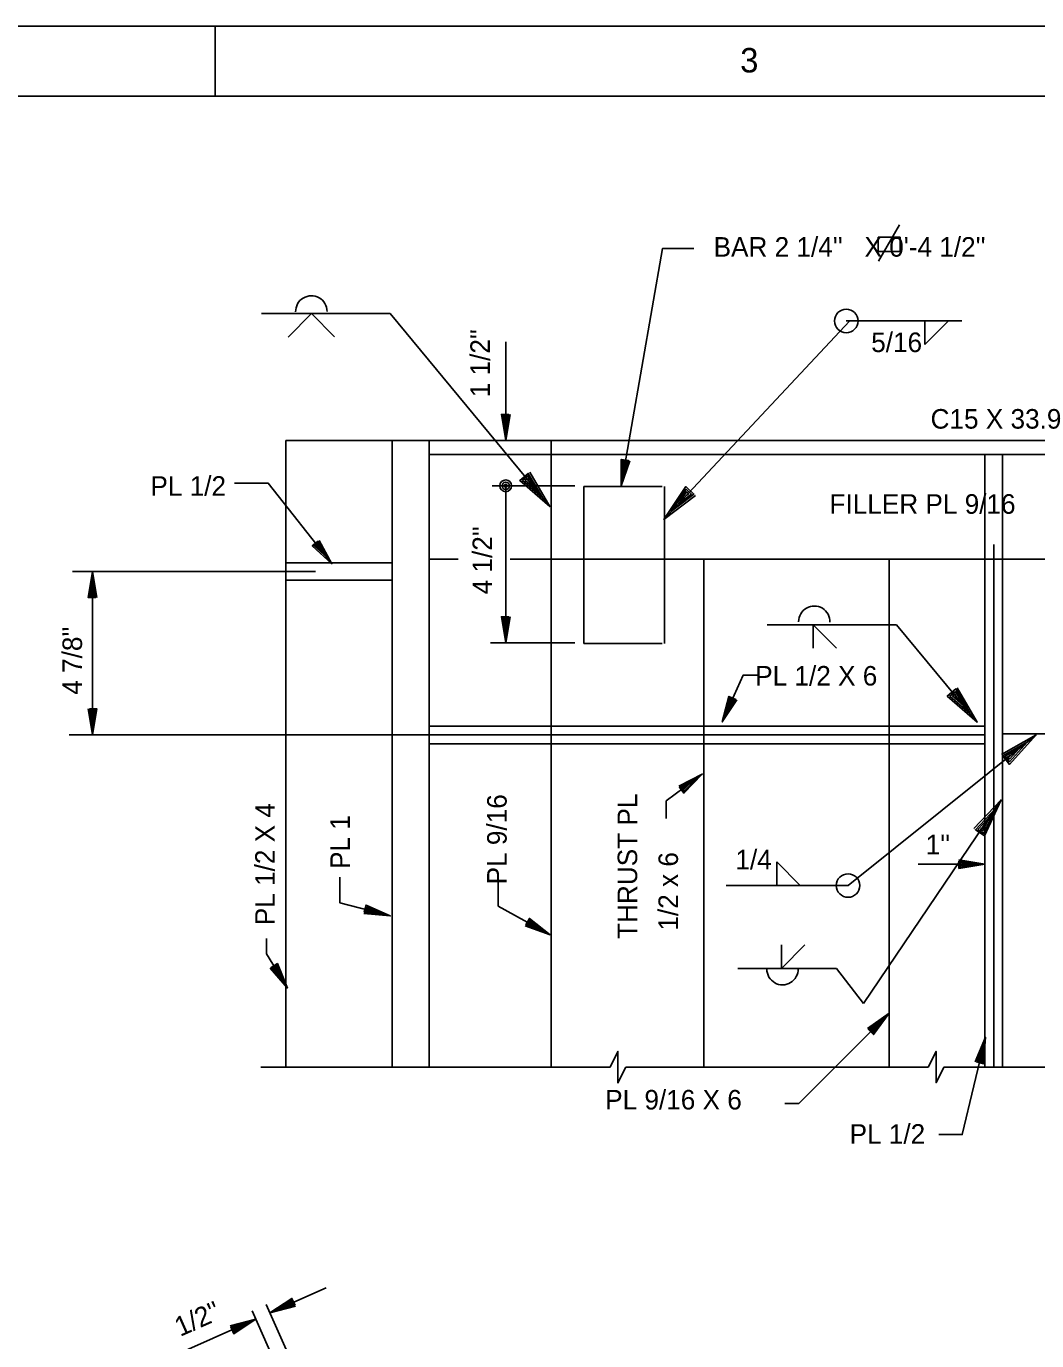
# Model space of a CAD drawing. Extents: x 0.1 to 13.5, y 0.1 to 9.5.
# Drawn here: x 5.215 to 7.629, y 6.319 to 9.458 of the extents above; entities that cross this region are included whole.
import ezdxf

# ---------------------------------------------------------------- set-up
doc = ezdxf.new("R2010")
doc.units = 0
for name, color, linetype in [('Level 1', 7, 'Continuous'), ('Level 13', 7, 'Continuous'), ('Level 25', 7, 'Continuous'), ('Level 3', 7, 'Continuous'), ('Level 50', 7, 'Continuous')]:
    doc.layers.add(name, color=color, linetype=linetype)

msp = doc.modelspace()

# ---------------------------------------------------------------- linework, layer by layer
at = {"layer": 'Level 1'}
for p, q in [((5.6667, 9.2917), (5.6667, 9.4583)), ((6.3284, 8.361), (6.5259, 8.361)), ((6.3244, 7.986), (6.5259, 7.986)), ((7.3455, 7.4575), (7.5053, 7.4575)), ((5.7753, 6.9726), (6.6097, 6.9726)), ((6.6471, 6.9726), (7.3699, 6.9726)), ((7.4072, 6.9726), (7.8241, 6.9726))]:
    msp.add_line(p, q, dxfattribs=at)
for points in [[(0.125, 9.4583), (13.4583, 9.4583), (13.4583, 0.125), (0.125, 0.125)], [(0.625, 9.2917), (13.2917, 9.2917), (13.2917, 0.2917), (0.625, 0.2917)]]:
    msp.add_lwpolyline(points, close=True, dxfattribs=at)
at = {"layer": 'Level 13'}
for points in [[(6.6471, 6.9726), (6.6284, 6.9351), (6.6284, 7.0101), (6.6097, 6.9726)], [(7.3699, 6.9726), (7.3885, 7.0101), (7.3885, 6.9352), (7.4072, 6.9726)]]:
    msp.add_lwpolyline(points, dxfattribs=at)
at = {"layer": 'Level 25'}
for p, q in [((7.3009, 8.9838), (7.2512, 8.8977)), ((7.3027, 8.9545), (7.2503, 8.9545)), ((7.2503, 8.9545), (7.2503, 8.9202)), ((7.3027, 8.9545), (7.3027, 8.9202)), ((7.3027, 8.9202), (7.2503, 8.9202)), ((6.0842, 8.7722), (5.7769, 8.7722)), ((5.8967, 8.7722), (5.8407, 8.7162)), ((5.8964, 8.7722), (5.8965, 8.7721)), ((5.8965, 8.7721), (5.9519, 8.7167)), ((6.0842, 8.7722), (6.4657, 8.3113)), ((7.1813, 8.7545), (6.7383, 8.2803)), ((7.174, 8.7546), (7.4498, 8.7546)), ((7.3615, 8.7546), (7.3615, 8.6984)), ((7.3615, 8.6984), (7.4173, 8.7542)), ((6.3606, 8.469), (6.3606, 8.7049)), ((5.8356, 8.469), (8.6378, 8.469)), ((5.8356, 8.469), (5.8356, 6.9726)), ((6.0894, 8.469), (6.0894, 6.9726)), ((6.1774, 8.469), (6.1774, 6.9726)), ((6.4689, 8.469), (6.4689, 6.9726)), ((6.1774, 8.4357), (8.6378, 8.4357)), ((7.5053, 8.4357), (7.5053, 6.9726)), ((7.547, 8.4357), (7.547, 6.9726)), ((6.3606, 8.361), (6.3606, 7.986)), ((6.7345, 8.3596), (6.547, 8.3596)), ((6.547, 7.9846), (6.547, 8.3596)), ((6.7397, 7.9846), (6.7397, 8.3596)), ((6.4491, 8.3314), (6.4491, 8.3314)), ((6.4657, 8.3113), (6.4657, 8.3113)), ((6.7561, 8.2993), (6.7561, 8.2993)), ((6.7383, 8.2803), (6.7383, 8.2803)), ((7.5261, 8.2205), (7.5261, 6.9726)), ((5.8356, 8.1773), (6.0894, 8.1773)), ((6.1774, 8.1857), (6.2473, 8.1857)), ((6.3713, 8.1857), (6.4689, 8.1857)), ((6.4689, 8.1857), (6.547, 8.1857)), ((6.547, 8.1857), (6.7397, 8.1857)), ((6.7397, 8.1857), (8.6378, 8.1857)), ((6.834, 8.1857), (6.834, 6.9726)), ((7.2761, 8.1857), (7.2761, 6.9726)), ((5.3254, 8.1565), (5.9065, 8.1565)), ((5.3738, 7.7659), (5.3738, 8.1565)), ((5.8356, 8.1357), (6.0894, 8.1357)), ((7.2941, 8.0293), (6.9847, 8.0293)), ((7.0947, 8.0293), (7.0947, 7.9731)), ((7.0947, 8.0293), (7.1506, 7.9733)), ((7.2941, 8.0293), (7.4868, 7.7966)), ((6.7345, 7.9846), (6.547, 7.9846)), ((7.4702, 7.8167), (7.4702, 7.8167)), ((6.1774, 7.7867), (6.834, 7.7867)), ((6.834, 7.7867), (7.2761, 7.7867)), ((7.2761, 7.7867), (7.5053, 7.7867)), ((7.4868, 7.7966), (7.4868, 7.7966)), ((5.3174, 7.7659), (7.5053, 7.7659)), ((7.1782, 7.4063), (7.6275, 7.7659)), ((7.547, 7.769), (7.8178, 7.769)), ((7.6275, 7.7659), (7.6275, 7.7659)), ((6.1774, 7.7451), (6.834, 7.7451)), ((6.834, 7.7451), (7.2761, 7.7451)), ((7.2761, 7.7451), (7.5053, 7.7451)), ((7.6072, 7.7497), (7.6072, 7.7497)), ((7.2154, 7.1245), (7.5438, 7.611)), ((7.5438, 7.611), (7.5438, 7.611)), ((7.5293, 7.5894), (7.5293, 7.5894)), ((7.0083, 7.4626), (7.0642, 7.4067)), ((7.0083, 7.4063), (7.0083, 7.4626)), ((6.887, 7.4063), (7.1782, 7.4063)), ((7.0189, 7.2084), (7.0189, 7.2647)), ((7.0189, 7.2084), (7.0749, 7.2644)), ((6.9149, 7.2084), (7.1504, 7.2084)), ((7.1504, 7.2084), (7.2154, 7.1245)), ((5.7973, 6.3858), (5.9318, 6.4456)), ((5.7883, 6.406), (6.0693, 5.7737)), ((5.7546, 6.391), (6.0356, 5.7587)), ((5.7636, 6.3708), (5.5597, 6.2802))]:
    msp.add_line(p, q, dxfattribs=at)
for points in [[(6.418, 8.3932), (6.4657, 8.3113), (6.3941, 8.3735), (6.4145, 8.3904), (6.4491, 8.3314), (6.4005, 8.3736), (6.4136, 8.3844), (6.4332, 8.3506), (6.4069, 8.3737), (6.4123, 8.3781), (6.4166, 8.3706)], [(6.8135, 8.3381), (6.7383, 8.2803), (6.7908, 8.3592), (6.8102, 8.3411), (6.7561, 8.2993), (6.7918, 8.3529), (6.8042, 8.3413), (6.7731, 8.3176), (6.7927, 8.3466), (6.7978, 8.3418), (6.7909, 8.3366)], [(7.4391, 7.8786), (7.4868, 7.7966), (7.4152, 7.8588), (7.4356, 7.8757), (7.4702, 7.8167), (7.4216, 7.8589), (7.4347, 7.8697), (7.4542, 7.8359), (7.428, 7.859), (7.4334, 7.8635), (7.4376, 7.856)], [(7.5448, 7.7196), (7.6275, 7.7659), (7.5642, 7.6954), (7.5476, 7.7161), (7.6072, 7.7497), (7.5641, 7.7018), (7.5535, 7.7151), (7.5876, 7.7341), (7.5641, 7.7082), (7.5598, 7.7137), (7.5673, 7.7178)], [(7.4787, 7.5422), (7.5438, 7.611), (7.5043, 7.5248), (7.4824, 7.5397), (7.5293, 7.5894), (7.5024, 7.5309), (7.4884, 7.5405), (7.5153, 7.5687), (7.5005, 7.5371), (7.4947, 7.541), (7.5007, 7.5472)]]:
    msp.add_lwpolyline(points, dxfattribs=at)
for centre in [(7.174, 8.7546), (7.1782, 7.4063)]:
    msp.add_circle(centre, 0.0281, dxfattribs=at)
for centre, start, end in [((5.8962, 8.7773), 0, 181.5792), ((7.0975, 8.0363), 358.4208, 180), ((7.0216, 7.2067), 180, 1.5792)]:
    msp.add_arc(centre, 0.0375, start, end, dxfattribs=at)
at = {"layer": 'Level 3'}
for p, q in [((6.6361, 8.3609), (6.6361, 8.3609)), ((6.6391, 8.378), (6.6391, 8.378)), ((5.9345, 8.1886), (5.9345, 8.1886)), ((5.9452, 8.175), (5.9452, 8.175)), ((6.8777, 7.7969), (6.8777, 7.7969)), ((6.8848, 7.8128), (6.8848, 7.8128)), ((6.0678, 7.3382), (6.0678, 7.3382)), ((6.0846, 7.3338), (6.0846, 7.3338)), ((6.4516, 7.2969), (6.4516, 7.2969)), ((6.4668, 7.2885), (6.4668, 7.2885)), ((5.83, 7.1762), (5.83, 7.1762)), ((5.839, 7.1614), (5.839, 7.1614)), ((7.5066, 7.0439), (7.5066, 7.0439)), ((7.5026, 7.0271), (7.5026, 7.0271))]:
    msp.add_line(p, q, dxfattribs=at)
for points in [[(6.8096, 8.928), (6.7352, 8.928), (6.6361, 8.3609)], [(6.657, 8.4205), (6.6361, 8.3609), (6.6366, 8.4241), (6.6541, 8.421), (6.6391, 8.378), (6.6395, 8.4209), (6.6506, 8.4189), (6.6419, 8.3944), (6.6423, 8.4177), (6.6469, 8.4169), (6.6449, 8.4115)], [(5.7129, 8.3671), (5.7934, 8.3671), (5.9452, 8.175)], [(5.9147, 8.2303), (5.9452, 8.175), (5.8985, 8.2175), (5.9124, 8.2284), (5.9345, 8.1886), (5.9028, 8.2175), (5.9116, 8.2245), (5.9242, 8.2017), (5.907, 8.2174), (5.9107, 8.2203), (5.9134, 8.2153)], [(6.9645, 7.9085), (6.9273, 7.9085), (6.8777, 7.7969)], [(6.9125, 7.8497), (6.8777, 7.7969), (6.8936, 7.8581), (6.9098, 7.8509), (6.8848, 7.8128), (6.8956, 7.8543), (6.9059, 7.8497), (6.8915, 7.828), (6.8975, 7.8505), (6.9018, 7.8486), (6.8986, 7.8438)], [(6.7436, 7.5665), (6.7436, 7.6083), (6.8299, 7.6723)], [(5.9644, 7.4264), (5.9644, 7.3653), (6.0846, 7.3338)], [(6.3427, 7.4146), (6.3427, 7.3574), (6.4668, 7.2885)], [(6.0217, 7.3396), (6.0846, 7.3338), (6.0269, 7.3596), (6.0224, 7.3425), (6.0678, 7.3382), (6.0287, 7.3557), (6.0258, 7.3448), (6.0517, 7.3424), (6.0304, 7.3518), (6.0292, 7.3473), (6.0349, 7.3468)], [(6.4073, 7.3097), (6.4668, 7.2885), (6.4173, 7.3278), (6.4087, 7.3123), (6.4516, 7.2969), (6.418, 7.3236), (6.4125, 7.3137), (6.4371, 7.305), (6.4187, 7.3194), (6.4165, 7.3153), (6.4219, 7.3134)], [(5.7888, 7.2796), (5.7888, 7.2434), (5.839, 7.1614)], [(5.7977, 7.2092), (5.839, 7.1614), (5.8153, 7.22), (5.8002, 7.2107), (5.83, 7.1762), (5.8138, 7.2159), (5.8042, 7.21), (5.8213, 7.1904), (5.8124, 7.2119), (5.8084, 7.2095), (5.8122, 7.2052)], [(7.0276, 6.8859), (7.0605, 6.8859), (7.2761, 7.1015)], [(7.3951, 6.8115), (7.4509, 6.8115), (7.5066, 7.0439)], [(7.482, 6.9857), (7.5066, 7.0439), (7.5021, 6.9809), (7.485, 6.985), (7.5026, 7.0271), (7.4995, 6.9843), (7.4885, 6.9869), (7.4987, 7.0109), (7.4969, 6.9876), (7.4924, 6.9887), (7.4947, 6.994)]]:
    msp.add_lwpolyline(points, dxfattribs=at)
at = {"layer": 'Level 50'}
for p, q in [((6.3606, 8.4863), (6.3606, 8.4863)), ((6.3606, 8.469), (6.3606, 8.469)), ((5.3738, 8.1565), (5.3738, 8.1565)), ((5.3738, 8.1392), (5.3738, 8.1392)), ((6.3606, 8.0034), (6.3606, 8.0034)), ((6.3606, 7.986), (6.3606, 7.986)), ((5.3738, 7.7832), (5.3738, 7.7832)), ((5.3738, 7.7659), (5.3738, 7.7659)), ((6.816, 7.662), (6.816, 7.662)), ((6.8299, 7.6723), (6.8299, 7.6723)), ((7.488, 7.4575), (7.488, 7.4575)), ((7.5053, 7.4575), (7.5053, 7.4575)), ((7.2761, 7.1015), (7.2761, 7.1015)), ((7.2639, 7.0893), (7.2639, 7.0893)), ((5.7973, 6.3858), (5.7973, 6.3858)), ((5.8131, 6.3928), (5.8131, 6.3928)), ((5.7477, 6.3637), (5.7477, 6.3637)), ((5.7636, 6.3708), (5.7636, 6.3708))]:
    msp.add_line(p, q, dxfattribs=at)
for points in [[(6.3709, 8.5313), (6.3606, 8.469), (6.3503, 8.5313), (6.3679, 8.5313), (6.3606, 8.4863), (6.3536, 8.5287), (6.3649, 8.5287), (6.3606, 8.503), (6.3569, 8.526), (6.3616, 8.526), (6.3606, 8.5203)], [(5.3842, 8.0942), (5.3738, 8.1565), (5.3635, 8.0942), (5.3812, 8.0942), (5.3738, 8.1392), (5.3668, 8.0968), (5.3782, 8.0968), (5.3738, 8.1225), (5.3702, 8.0995), (5.3748, 8.0995), (5.3738, 8.1052)], [(6.3709, 8.0484), (6.3606, 7.986), (6.3503, 8.0484), (6.3679, 8.0484), (6.3606, 8.0034), (6.3536, 8.0457), (6.3649, 8.0457), (6.3606, 8.02), (6.3569, 8.043), (6.3616, 8.043), (6.3606, 8.0374)], [(5.3635, 7.8282), (5.3738, 7.7659), (5.3842, 7.8282), (5.3665, 7.8282), (5.3738, 7.7832), (5.3808, 7.8256), (5.3695, 7.8256), (5.3738, 7.7999), (5.3775, 7.8229), (5.3728, 7.8229), (5.3738, 7.8172)], [(6.7737, 7.6435), (6.8299, 7.6723), (6.786, 7.6269), (6.7754, 7.6411), (6.816, 7.662), (6.7861, 7.6311), (6.7794, 7.6402), (6.8026, 7.6521), (6.7863, 7.6354), (6.7835, 7.6392), (6.7887, 7.6417)], [(7.443, 7.4679), (7.5053, 7.4575), (7.443, 7.4472), (7.443, 7.4649), (7.488, 7.4575), (7.4456, 7.4505), (7.4456, 7.4619), (7.4713, 7.4575), (7.4483, 7.4539), (7.4483, 7.4585), (7.454, 7.4575)], [(7.2248, 7.0648), (7.2761, 7.1015), (7.2394, 7.0502), (7.2269, 7.0626), (7.2639, 7.0893), (7.2389, 7.0544), (7.2309, 7.0624), (7.2521, 7.0775), (7.2384, 7.0586), (7.2351, 7.0619), (7.2398, 7.0652)], [(5.8584, 6.4016), (5.7973, 6.3858), (5.85, 6.4205), (5.8572, 6.4044), (5.8131, 6.3928), (5.8489, 6.4164), (5.8535, 6.406), (5.8283, 6.3996), (5.8478, 6.4123), (5.8497, 6.408), (5.8442, 6.4066)], [(5.7024, 6.3549), (5.7636, 6.3708), (5.7108, 6.336), (5.7036, 6.3522), (5.7477, 6.3637), (5.7119, 6.3401), (5.7073, 6.3505), (5.7325, 6.357), (5.713, 6.3443), (5.7111, 6.3485), (5.7167, 6.3499)]]:
    msp.add_lwpolyline(points, dxfattribs=at)
for radius in [0.0141, 0.00879, 0.00352]:
    msp.add_circle((6.3606, 8.361), radius, dxfattribs=at)

# ---------------------------------------------------------------- texts
at = {"layer": 'Level 1'}
msp.add_text('3', height=0.0584, dxfattribs=at).set_placement((6.9206, 9.3481))
at = {"layer": 'Level 25'}
for s, height, p in [("BAR 2 1/4''   X 0'-4 1/2''", 0.046698, (6.8571, 8.9081)), ('5/16', 0.0467, (7.2335, 8.6803)), ('C15 X 33.9', 0.0467, (7.3754, 8.4975)), ('PL 1/2', 0.0467, (5.5118, 8.3372)), ('FILLER PL 9/16', 0.046698, (7.134, 8.2942)), ('PL 1/2 X 6', 0.0467, (6.9565, 7.8839)), ("1''", 0.0467, (7.3635, 7.4808)), ('1/4', 0.0467, (6.9092, 7.4451)), ('PL 9/16 X 6', 0.046698, (6.5981, 6.8715)), ('PL 1/2', 0.0467, (7.1819, 6.7897))]:
    msp.add_text(s, height=height, dxfattribs=at).set_placement(p)
for s, rotation, p in [("1 1/2''", 90, (6.3227, 8.5724)), ("4 1/2''", 90, (6.328, 8.1017)), ("4 7/8''", 90, (5.3485, 7.862)), ('PL 1/2 X 4', 90, (5.8088, 7.3116)), ('PL 9/16', 90, (6.3628, 7.4091)), ('THRUST PL', 90, (6.6746, 7.2789)), ('PL 1', 90, (5.9884, 7.4459)), ('1/2 x 6', 90, (6.772, 7.2987)), ("1/2''", 23.9622, (5.5828, 6.3282))]:
    msp.add_text(s, height=0.0467, rotation=rotation, dxfattribs=at).set_placement(p)

doc.saveas('drawing.dxf')
